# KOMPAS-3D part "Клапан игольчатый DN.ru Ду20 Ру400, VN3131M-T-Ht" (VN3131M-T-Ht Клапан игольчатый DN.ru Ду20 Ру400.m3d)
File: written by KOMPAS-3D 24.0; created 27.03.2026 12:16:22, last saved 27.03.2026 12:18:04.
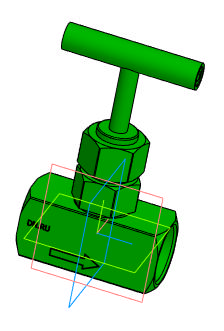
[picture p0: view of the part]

Document properties: Автор: Илья; Полное имя файла: D:\Обмен\Заказы с фриланса\DN.ru\VNxxM-T-Ht Клапан игольчатый DN.ru Ду8-50 Ру400\VN3131M-T-Ht Клапан игольчатый DN.ru Ду8-50 Ру400\DN20\VN3131M-T-Ht Клапан игольчатый DN.ru Ду20 Ру400.m3d

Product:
- Body: Body9  | qty 1
    Масса: 0.433192
- Part/product: Клапан игольчатый DN.ru Ду20 Ру400  | designation VN3131M-T-Ht
    Масса: 0.5
    Раздел спецификации: Прочие изделия
    Примечание: D090-02132

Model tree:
1. Body9  (labels: Body9)

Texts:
  VN3131M-T-Ht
